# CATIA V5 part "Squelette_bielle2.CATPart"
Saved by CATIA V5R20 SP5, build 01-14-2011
Part number: Squelette_bielle2
Publications: "Point.1", "Droite.1", "Droite.2", "Plan.1"
Bounding box of the stored display mesh (mm): x -10 to 10, y 0 to 40, z 0 to 0
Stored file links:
  F:\PROJ IAO\CATIA\Squelette_bielle2.CATPart
  F:\PROJ IAO\CATIA\Assemblage Squelette.CATProduct
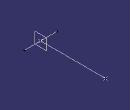
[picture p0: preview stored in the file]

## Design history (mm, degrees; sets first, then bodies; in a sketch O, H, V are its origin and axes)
Set1
  Point1: linked copy from another document
Set2
  Plane1: type Offset, RefPlane yz-plane, Offset 0
  Point2: type OnPlane, Support Plane1, H 40, V 0, Direction (0, 1, 0)
  Line1: type PtPt, FirstPoint Point2, SecondPoint Point1
  Line2: type PtDir, RefPoint Point1, Direction Plane1, Start -10, End 10
Body1 (main body)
